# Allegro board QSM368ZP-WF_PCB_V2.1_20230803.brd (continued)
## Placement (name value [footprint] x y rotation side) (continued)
TP1304  TP_1_00mm  [TP_1_00]  19.7 47.75 0 top
TP1401  RESET_N  [TP_1_00]  41.45 30.75 0 top
TP1402  PON_1  [TP_1_00]  38.02 30.75 0 top
TP1403  VOL_DOWN  [TP_1_00]  42.33 29.38 0 top
TP1404  ESC  [TP_1_00]  40.5 29.38 0 top
TP1405  MENU  [TP_1_00]  39.52 30.75 0 top
U0101  -  [ETA1654FSG]  28.65 84.28 180 bottom
U0103  -  [ETA1654FSG]  52.52 85.25 180 bottom
U0104  -  [ETA1654FSG]  35.12 65.38 90 bottom
U0201  NM-ICMEF112P900MFR  [ICMEF112P900MFR]  78.75 92.22 90 top
U0202  SGM2036S-2_8XN5G_TR  [SGM2036S-2_8XN5G_TR_PINS5_2D92X1D6]  81.42 89.65 180 bottom
U0203  SGM2036S-2_8XN5G_TR  [SGM2036S-2_8XN5G_TR_PINS5_2D92X1D6]  77.53 89.6 180 bottom
U0204  -  [ETA3415S6G]  87.58 89.95 180 bottom
U0205  SGM2036S-ADJXN5G/TR  [SGM2036S-ADJXN5G_TR_PINS5_2D92X1D6]  73.88 89.62 180 bottom
U0206  NM-ICMEF112P900MFR  [ICMEF112P900MFR]  97.6 92.12 90 top
U0207  NM-ICMEF112P900MFR  [ICMEF112P900MFR]  93.9 92.12 90 top
U0208  NM-ICMEF112P900MFR  [ICMEF112P900MFR]  82.45 92.25 90 top
U0209  NM-ICMEF112P900MFR  [ICMEF112P900MFR]  90.2 92.12 90 top
U0210  NM-ICMEF112P900MFR  [ICMEF112P900MFR]  86.15 92.22 90 top
U0304  -  [WS4612EDA-5_TR]  33.15 17.18 90 bottom
U0403  NM-ICMEF112P900MFR  [ICMEF112P900MFR]  14.88 16.45 270 top
U0404  NM-ICMEF112P900MFR  [ICMEF112P900MFR]  7.28 16.45 270 top
U0405  -  [PNMT60V02]  6.65 19.12 0 bottom
U0407  NM-PNMT60V02  [PNMT60V02]  49.77 96.08 180 bottom
U0408  NM-ICMEF112P900MFR  [ICMEF112P900MFR]  3.48 16.43 270 top
U0409  SGM3756YTDI6G/TR  [SGM3756YTDI6G_TR_PINS7_2X2]  70.28 87.7 0 top
U0410  NM-PNMT60V02  [PNMT60V02]  51.77 93.08 0 bottom
U0411  NM-ICMEF112P900MFR  [ICMEF112P900MFR]  11.07 16.45 270 top
U0413  -  [PNMT60V02]  10.18 19.18 0 bottom
U0501  SGM2036S-2_8XN5G_TR  [SGM2036S-2_8XN5G_TR_PINS5_2D92X1D6]  64.83 86.78 180 bottom
U0502  SGM2036S-2_8XN5G_TR  [SGM2036S-2_8XN5G_TR_PINS5_2D92X1D6]  17.57 96.92 270 top
U0503  NM-ETA5053V180DF1E  [ETA5053V180DF1E]  15.6 92.4 90 top
U0504  SGM3756YTDI6G/TR  [SGM3756YTDI6G_TR_PINS7_2X2]  62.58 71 0 bottom
U0601  NM-WS4612EDA-5_TR  [WS4612EDA-5_TR]  77.47 26.7 90 bottom
U0602  NM-WS4612EDA-5_TR  [WS4612EDA-5_TR]  39.42 22.73 90 bottom
U0603  NM-WS4612EDA-5_TR  [WS4612EDA-5_TR]  70.22 26.65 90 bottom
U0604  -  [ETA1654FSG]  38.1 49.25 90 bottom
U0701  -  [ETA1654FSG]  69.25 32.92 180 bottom
U0702  -  [TXB0104PWR]  91.45 60.05 90 bottom
U0901  -  [G2401CG]  104.42 29 0 bottom
U0902  -  [YT8531C]  104.67 43.52 90 bottom
U1001  NM-CS86552E  [CS86552E]  12.62 67.17 90 bottom
U1002  WMM7037ATSN0-4/TR  [WMM7037ATSN0]  15.35 88.05 270 top
U1101  NM-SIT3088EESA  [SIT3088EESA]  104.53 64.1 90 bottom
U1102  -  [LSF0204YZPR]  103.75 56.88 180 bottom
U1103  NM-UM3232EEUE  [UM3232EEUE]  107.12 75.25 0 bottom
U1201  Stud_Mechanical-tooth_M2_L4.35_XD_R1  [TP-NUU-M3_15X6_00X4_35MM]  73.15 40.08 180 bottom
U1202  Stud_Mechanical-tooth_M2_L4.35_XD_R1  [TP-NUU-M3_15X6_00X4_35MM]  19.15 40.08 180 bottom
U1203  Stud_Mechanical-tooth_M2_L4.35_XD_R1  [TP-NUU-M3_15X6_00X4_35MM]  73.15 66.08 180 bottom
U1204  NM-X1B000311000100  [X1B000311000100_PINS10_3D2X2D5]  85.1 70.2 270 bottom
U1205  Stud_Mechanical-tooth_M2_L4.35_XD_R1  [TP-NUU-M3_15X6_00X4_35MM]  19.15 66.08 180 bottom
U1301  SG368ZWFNA-G55-UNNNA  [SG368Z]  46.15 53.08 180 top
U1401  U.FL-R-SMT-1(80)  [RF-CON-818000117]  30.85 25.43 180 top
X0901  -  [Q22FA1280021400]  111.45 43.02 270 bottom

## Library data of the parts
B0101 B0503 B1002 = B
B0201 B0202 B0203 B0204 B0205 B0206 R0116 R0203 R0204 R0209 R0223 R0229 R0309 R0607 R0618 R0624 R0936 R1455 R1466-R1469 = R-0402_0R
B0501 B0502 = R-0402_NM
B0901 B1001 B1003-B1005 = B-0603_H0_95
BAT1201 = MS621FE-FL11E_0
C0102 C0103 C0104 C0112 C0119 C0122 C0124 C0128 C0211 C0303 C0319 C0404 C0406 C0413 C0502 C0506 C0516 C0519 C0524 C0526 C0601 C0602 C0606 C0607 C0609 C0613 C0614 C0619 C0701 C0702 C0705 C0706 C0708 C0709 C0714 C0715 C0716 C0802 C0803 C0804 C0805 C0806 C0901 C0903 C0909 C0912 C0920 C0921 C1001 C1004 C1005 C1007 C1008 C1010-C1012 C1015-C1017 C1021 C1103-C1105 C1110 C1111 C1113 C1204 C1304 = C
C0105 C0106 C0107 C0109 C0123 C0126 C0352 C0354 C0363 C0401 C0402 C0410 C0512 C0605 C0611 C0615 C0623 C1302 = c-0603_22_47uf_H1_00
C0108 C0110 C0115 C0116 C0118 C0121 C0127 C0520 C0522 C0622 C0624 C0704 C1055 C1056 = C-0805_H1_45
C0111 C0113 C0114 C0353 C0355 C0360 C0361 C0362 C0618 C0620 C0621 = C: signal model: C_C-0402_100NF_+/-10%_16V_100nF_+/-10%_16V
C0201 C0202 C0210 C0214 C0299 C0403 C0405 C0408 C0501 C0507 C0511 C0514 C0517 C0518 C0527 C0528 C0530 C0533 C1006 C1009 C1023 C1025 C1099 C1101 C1106 = C-0402
C0203 C0206 C0407 C0409 C0508 C0521 C0523 = C-0603
C0204 C0207 C0209 C0212 C0213 C0215 C0216 C0217 C0535 C0711 C0902 C0911 C0916 C0917 C0918 = C-0402_X5R_10UF
C0205 C0208 = c-0402_4_7_10uf_H0_70
C0301 C0307 C0309 C0707 C0801 C0904 C0905 C0906 C0907 C0908 C0910 C0913 C0914 C0915 C0919 C0922 C0986 C0987 C0988 C1014 C1024 C1102 C1108 = C: signal model: C_C-0402_100NF_+/-10%_10V_100nF_+/-10%_10V
C0412 C0504 = C-0805
C0505 C0509 C0510 C0513 C0515 C0525 C0529 C0531 C0532 C0534 C0536 C0603 C0604 C0617 C1003 C1201-C1203 = C: signal model: C_C-0402_NM_100NF_+/-10%_16V_NM_100nF_+/-10%_16V
C0703 = C: signal model: C_C-0402_NM_220NF_+/-10%_10V_NM_220nF_+/-10%_10V
C0710 C1333 = C-3528TB-M
C0712 C0713 = c-0603_22_47uf_H1_00: signal model: C_C-0402_100NF_+/-10%_10V_100nF_+/-10%_10V
C0717 = C-0805_H1_45: signal model: C_C-0402_NM_220NF_+/-10%_10V_NM_220nF_+/-10%_10V
C1013 = C-1210
C1018 C1020 C1022 C1026 C1027 = C-0603_H1_00
C1303 = C-3528TB-M: signal model: DEFAULT_CAPACITOR_1e+08pF_2_1
C1306 = C: signal model: DEFAULT_CAPACITOR_100000pF_2_1
C1401 C1402 = C-0402_X5R_1UF
D0101 = SMAJ18CA
D0102 D0705 D0706 = LTST-C193KRKT-5A
D0301 D0359 D0904 D0906 = ESD5304D-10_TR
D0302 D0303 D0353 D0356 D0357 D0601 D0603 D0606 D0608 D0702 D0704 D0801 D0802 D0804 D0807 D0808 D0809 D0810 D0901 D0903 = ESDU5V0F1
D0354 D0355 D0358 D0602 D0605 = PTVSHC2EN7VU
D0401 D0402 = PSBD3D40V1H
D0403 D0405 D0508 = RB160VA-40
D0404 Q0405 U0405 U0407 U0410 U0413 = PNMT60V02
D0406 D0407 D0408 D0410 = PESDNC2FD7VB
D0501 D0503 D0505 D0507 D0701 D0703 D0902 D0905 Q0402 Q0403 Q0404 Q1101 Q1102 = DTC043ZEBTL
D0502 D0506 D0511 D0512 D0514 U0201 U0206 U0207 U0208 U0209 U0210 U0403 U0404 U0408 U0411 = ICMEF112P900MFR
D0504 D0509 D0510 D0513 D1104 D1106 = PESD5V0S1BL
D0803 = F-CESDLC5V0M5
D0806 D1001-D1004 D1050 D1051 D1201 D1202 D1255 D1256 = PESDNC2FD5VBH
D1301 = PTVSHC3N4V5B
F0101 = 2410WNF1000A125V
HOLE1201-HOLE1206 = PTH_cir2_50_4_50
J0101 = DC-305B209
J0102 = C2542VD10210G0101PK
J0201 J0202 = FH26W-25S-0_3SHW_60
J0301 = W-N3-SC90-012
J0302 = WX4558105890
J0401 = WXHDMI2034A36
J0402 = 50552-00601-001
J0403 = 50552-04001-001
J0501 = AXE530127
J0502 = 50552-03001-001
J0503 = 6298706220883
J0601 = W-USB2-SZ90-A10
J0701 = MINI-PCIE-CON
J0702 = 480995701
J0801 = MUP-M615-1
J0802 = MUP-C792-3
J0901 = 11201208210120021
J1001 = C2001VD10601T0101PB
J1002 = KR-CKX-3_5-335D-F
J1101 = PH2542-3-115D30T
J1201 = C2012VD21222T0101PC
L0101 L0102 L0103 L0201 L0401 L0501 L0601 L0701 = L
L0702 = SDMM0806H-2-900T
L0901 = L-2016
LAB1201 = SILKLABEL_25_00x10_00
PCB1201 = BOARD_PCB
Q0401 = WPM3027
Q0501 Q0502 = DMG2305UX-7
R0101 R0102 R0103 R0104 R0105 R0108 R0110 R0112 R0113 R0114 R0115 R0117 R0207 R0208 R0212 R0214 R0219 R0221 R0222 R0224 R0226 R0227 R0228 R0305 R0308 R0313 R0325 R0401 R0402 R0403 R0404 R0405 R0407 R0409 R0413 R0414 R0415 R0416 R0417 R0420 R0421 R0422 R0424 R0425 R0426 R0427 R0428 R0429 R0430 R0503 R0504 R0505 R0506 R0507 R0508 R0510 R0512 R0513 R0515 R0517 R0518 R0519 R0522 R0523 R0528 R0529 R0530 R0602 R0603 R0604 R0606 R0610 R0612 R0613 R0614 R0615 R0617 R0620 R0622 R0623 R0698 R0699 R0701 R0702 R0704 R0705 R0706 R0707 R0708 R0710 R0711 R0714 R0716 R0717 R0718 R0719 R0720 R0722 R0723 R0724 R0725 R0727 R0729 R0731 R0732 R0807 R0809 R0866 R0901 R0902 R0904 R0905 R0907 R0908 R0909 R0911 R0912 R0913 R0914 R0916 R0917 R0918 R0919 R0921 R0922 R0924 R0925 R0926 R0927 R0928 R0929 R0934 R0938 R0940 R0941 R0942 R0943 R0944 R0946 R0947 R0952 R0953 R0956 R1004 R1007 R1011 R1014 R1015 R1017 R1022 R1024 R1103 R1105 R1107 R1111 R1113 R1117 R1120 R1123 R1129 R1132-R1134 R1203 R1204 R1206-R1208 R1301 R1456 = R-0402
R0106 R0120 = R-1206
R0166 R0406 R0418 R0644 R0703 R0709 R0713 R0733 R0933 R0935 R0948 R0950 R0951 R0988 R1125 R1155 R1157 R1159 R1161 R1202 R1205 R1210 R1211 R1457 = R-0402: signal model: R-0402_R-0402_NM_0R_+/-5%_1/16W_NM_0R_+/-5%_1/16W
R0255 R0256 R0257 R0258 R0259 R0260 R0261 R0262 R0263 R0264 R0265 R0266 R0319 R0322 R0323 R0340 R0341 R0455 R0457 R0458 R0459 R0460 R0461 R0462 R0466 R0511 R0526 R0566 R0567 R0568 R0569 R0570 R0571 R0572 R0573 R0574 R0575 R0601 R0608 R0611 R0616 R0619 R0621 R0721 R0726 R0805 R0910 R0915 R0923 R0930 R0931 R0939 R0949 R0954 R1003 R1010 R1018 R1023 R1099 R1115 R1119 R1126 R1130 R1156 R1158 R1160 R1162 R1407 = R-0402: signal model: R-0402_R-0402_0R_+/-5%_1/16W_0R_+/-5%_1/16W
R0302 R0312 R0516 R0527 R0804 = R
R0366 R0408 R0509 R0525 R0666 R0677 R0678 R0715 R0728 R0803 R0808 R0810 R0813 R1005 R1012 R1121 = R-0603
R0712 R0730 R0801 R0802 R0806 R0811 R0814 = R-0402: signal model: R-0402_R-0402_33R_+/-5%_1/16W_33R_+/-5%_1/16W
R0903 R0906 R0920 R0932 R0945 R0955 R1302-R1307 = R-0402: signal model: R-0402_R-0402_22R_+/-5%_1/16W_22R_+/-5%_1/16W
R1002 R1008 R1016 R1019-R1021 = R-0805
R1401-R1406 R1408 R1409 = R-0402: signal model: DEFAULT_RESISTOR_2.200000OHM_2_1
S0301 S1201 = SSAJ120100
S1202 = THDP08-060AB1
TP0101 TP0102 TP0103 TP0301 TP0302 TP0303 TP0502 TP0504 TP1201-TP1203 TP1301-TP1304 TP1401-TP1405 = TP_1_00
TP0104 = TP_2_20
TP0501 TP0503 TP0701 TP0702 TP0703 = TP
U0101 U0103 U0104 U0604 U0701 = ETA1654FSG
U0202 U0203 U0501 U0502 = SGM2036S-2_8XN5G_TR
U0204 = ETA3415S6G
U0205 = SGM2036S-ADJXN5G_TR
U0304 U0601 U0602 U0603 = WS4612EDA-5_TR
U0409 U0504 = SGM3756YTDI6G_TR
U0503 = ETA5053V180DF1E
U0702 = TXB0104PWR
U0901 = FC1503NL
U0902 = YT8531C
U1001 = CS86552E
U1002 = WMM7037ATSN0
U1101 = SIT3088EESA
U1102 = LSF0204YZPR
U1103 = UM3232EEUE
U1201-U1203 U1205 = tp-nuu-m3_15x6_00x4_35mm
U1204 = X1B000311000100
U1301 = SG368Z
U1401 = RF-CON-818000117
X0901 = Q22FA1280021400

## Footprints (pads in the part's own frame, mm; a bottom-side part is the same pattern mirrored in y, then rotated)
2410WNF1000A125V
  rect 1.96x3.15 smd: 1(-2.455,0) 2(2.455,0)
3528TB-M
  rect 1.45x2.8 smd: 1(-1.325,0) 2(1.325,0)
50552-00601-001_PINS8_7D5X3D4
  rect 0.4x1.6 smd: 1(-1.25,1.3) 2(-0.75,-1.1) 3(-0.25,1.3) 4(0.25,-1.1) 5(0.75,1.3) 6(1.25,-1.1)
  rect 1.4x2.9 smd: 7(-2.95,0.1) 8(2.95,0.1)
50552-03001-001_PINS32_19D5X3D4
  rect 0.4x1.6 smd: 1(-7.25,1.3) 2(-6.75,-1.1) 3(-6.25,1.3) 4(-5.75,-1.1) 5(-5.25,1.3) 6(-4.75,-1.1) 7(-4.25,1.3) 8(-3.75,-1.1) 9(-3.25,1.3) 10(-2.75,-1.1) 11(-2.25,1.3) 12(-1.75,-1.1) 13(-1.25,1.3) 14(-0.75,-1.1) 15(-0.25,1.3) 16(0.25,-1.1) 17(0.75,1.3) 18(1.25,-1.1) 19(1.75,1.3) 20(2.25,-1.1) 21(2.75,1.3) 22(3.25,-1.1) 23(3.75,1.3) 24(4.25,-1.1) 25(4.75,1.3) 26(5.25,-1.1) 27(5.75,1.3) 28(6.25,-1.1) 29(6.75,1.3) 30(7.25,-1.1)
  rect 1.4x2.9 smd: 31(-8.95,0.1) 32(8.95,0.1)
50552-04001-001_PINS42_24D5X3D4
  rect 0.4x1.6 smd: 1(-9.75,1.3) 2(-9.25,-1.1) 3(-8.75,1.3) 4(-8.25,-1.1) 5(-7.75,1.3) 6(-7.25,-1.1) 7(-6.75,1.3) 8(-6.25,-1.1) 9(-5.75,1.3) 10(-5.25,-1.1) 11(-4.75,1.3) 12(-4.25,-1.1) 13(-3.75,1.3) 14(-3.25,-1.1) 15(-2.75,1.3) 16(-2.25,-1.1) 17(-1.75,1.3) 18(-1.25,-1.1) 19(-0.75,1.3) 20(-0.25,-1.1) 21(0.25,1.3) 22(0.75,-1.1) 23(1.25,1.3) 24(1.75,-1.1) 25(2.25,1.3) 26(2.75,-1.1) 27(3.25,1.3) 28(3.75,-1.1) 29(4.25,1.3) 30(4.75,-1.1) 31(5.25,1.3) 32(5.75,-1.1) 33(6.25,1.3) 34(6.75,-1.1) 35(7.25,1.3) 36(7.75,-1.1) 37(8.25,1.3) 38(8.75,-1.1) 39(9.25,1.3) 40(9.75,-1.1)
  rect 1.4x2.9 smd: 41(-11.45,0.1) 42(11.45,0.1)
480995701
  round 1.6 hole 1.6 unplated: (-12.1,0)
  round 1.1 hole 1.1 unplated: (12.1,0)
  rect 4.8x3 smd: 1(-12.1,-3.15) 2(12.1,-3.15) 3(12.1,3.15) 4(-12.1,3.15)
6298706220883
  rect 0.3x1.1 smd: 1(1.25,0) 2(0.75,0) 3(0.25,0) 4(-0.25,0) 5(-0.75,0) 6(-1.25,0)
  rect 0.42x1.3 smd: 7(-2.47,-2.87) 8(2.47,-2.87)
11201208210120021
  round 3.35 hole 3.35 unplated: (-6.35,-0.06) (6.35,-0.06)
  round 1.5 hole 0.9: 1(3.57,2.48) 2(2.55,4.26) 3(1.53,2.48) 4(0.51,4.26) 5(-0.51,2.48) 6(-1.53,4.26) 7(-2.55,2.48) 8(-3.57,4.26)
  round 1.7 hole 1: 9(6.86,9.07) 10(4.57,9.07) 11(-4.57,9.07) 12(-6.86,9.07)
  round 3.2 hole 1.8: 15(8.13,3.5) 16(-8.13,3.5)
AXE530127
  rect 0.23x0.5 smd: 1(2.8,1.2) 2(2.4,1.2) 3(2,1.2) 4(1.6,1.2) 5(1.2,1.2) 6(0.8,1.2) 7(0.4,1.2) 8(0,1.2) 9(-0.4,1.2) 10(-0.8,1.2) 11(-1.2,1.2) 12(-1.6,1.2) 13(-2,1.2) 14(-2.4,1.2) 15(-2.8,1.2) 16(-2.8,-1.2) 17(-2.4,-1.2) 18(-2,-1.2) 19(-1.6,-1.2) 20(-1.2,-1.2) 21(-0.8,-1.2) 22(-0.4,-1.2) 23(0,-1.2) 24(0.4,-1.2) 25(0.8,-1.2) 26(1.2,-1.2) 27(1.6,-1.2) 28(2,-1.2) 29(2.4,-1.2) 30(2.8,-1.2)
  custom 0.225x0.225 smd: 31(-3.8,-0.99) 32(3.8,-0.99) 33(3.8,0.99) 34(-3.8,0.99)
B-0402
  rect 0.55x0.55 smd: 1(-0.45,0) 2(0.45,0)
B-0603_H0_95
  rect 0.7x0.9 smd: 1(-0.75,0) 2(0.75,0)
BOARD_PCB
  round 0.4 smd: 1(0,0)
C2001VD10601T0101PB
  rect 1.65x1.65 hole 0.85: 1(-5,-0.625)
  round 1.65 hole 0.85: 2(-3,-0.625) 3(-1,-0.625) 4(1,-0.625) 5(3,-0.625) 6(5,-0.625)
C2012VD21222T0101PC
  rect 1.4x1.4 hole 0.8: 1(-11,0.625)
  round 1.4 hole 0.8: 2(-11,-1.375) 3(-9,0.625) 4(-9,-1.375) 5(-7,0.625) 6(-7,-1.375) 7(-5,0.625) 8(-5,-1.375) 9(-3,0.625) 10(-3,-1.375) 11(-1,0.625) 12(-1,-1.375) 13(1,0.625) 14(1,-1.375) 15(3,0.625) 16(3,-1.375) 17(5,0.625) 18(5,-1.375) 19(7,0.625) 20(7,-1.375) 21(9,0.625) 22(9,-1.375) 23(11,0.625) 24(11,-1.375)
C2542VD10210G0101PK
  rect 1.82x1.82 hole 1.02: 1(-1.27,0)
  round 1.82 hole 1.02: 2(1.27,0)
C-0402
  rect 0.55x0.55 smd: 1(-0.45,0) 2(0.45,0)
C-0402_4_7_10UF
  rect 0.525x0.7 smd: 1(-0.463,0) 2(0.463,0)
C-0402_4_7_10UF_H0_70
  rect 0.525x0.7 smd: 1(-0.463,0) 2(0.463,0)
C-0603
  rect 0.7x0.8 smd: 1(-0.75,0) 2(0.75,0)
C-0603_22_47UF_H1_00
  rect 0.7x0.96 smd: 1(-0.75,0) 2(0.75,0)
C-0603_H1_00
  rect 0.7x0.8 smd: 1(-0.75,0) 2(0.75,0)
C-0805
  rect 0.9x1.3 smd: 1(-0.9,0) 2(0.9,0)
C-0805_H1_45
  rect 0.9x1.3 smd: 1(-0.9,0) 2(0.9,0)
C-1206
  rect 1.3x1.6 smd: 1(-1.4,0) 2(1.4,0)
C-1210
  rect 1.2x2 smd: 1(-1.6,0) 2(1.6,0)
CS86552E
  rect 1.215x0.23 smd: 1(-2.567,2.223) 2(-2.567,1.587) 3(-2.567,0.953) 4(-2.567,0.318) 5(-2.567,-0.318) 6(-2.567,-0.953) 7(-2.567,-1.587) 8(-2.567,-2.223) 9(2.567,-2.223) 10(2.567,-1.587) 11(2.567,-0.953) 12(2.567,-0.318) 13(2.567,0.318) 14(2.567,0.953) 15(2.567,1.587) 16(2.567,2.223)
  rect 2.4x3.7 smd: 17(0,0)
DC-305B209
  round 2.4 hole 2.4 unplated: (-1.9,-1.3)
  oval 3.5x2.6 hole 1.7x0.8: 1(4.4,-4.7) 2(4.4,4) 3(4.4,-1.3)
  oval 3.9x2.4 hole 2.1x0.6: 4(-2.9,-4.95) 5(-2.9,4.95)
DMG2305UX-7
  rect 0.8x0.9 smd: 1(-0.95,-1) 2(0.95,-1) 3(0,1)
DTC043ZEBTL
  rect 0.46x0.65 smd: 1(-0.5,-0.525) 2(0.5,-0.525) 3(0,0.525)
ESD5304D-10_TR
  rect 0.2x0.6 smd: 1(-1,-0.4) 2(-0.5,-0.4) 4(0.5,-0.4) 5(1,-0.4) 6(1,0.4) 7(0.5,0.4) 9(-0.5,0.4) 10(-1,0.4)
  rect 0.4x0.7 smd: 3(0,-0.35) 8(0,0.35)
ESDU5V0F1
  rect 0.5x0.4 smd: 1(-0.4,0)
  rect 0.62x0.4 smd: 2(0.34,0)
ETA1654FSG
  rect 0.45x0.3 smd: 1(-0.675,0.5) 2(-0.675,0) 3(-0.675,-0.5) 4(0.675,-0.5) 5(0.675,0) 6(0.675,0.5)
ETA3415S6G
  rect 0.7x0.3 smd: 1(-0.75,0.5) 2(-0.75,0) 3(-0.75,-0.5) 4(0.75,-0.5) 5(0.75,0) 6(0.75,0.5)
ETA5053V180DF1E
  custom 0.077x0.077 smd: 1(-0.375,-0.41) 2(0.375,-0.41) 3(0.375,0.41) 4(-0.375,0.41)
  rect 0.42x0.42 smd rot 45: 5(0,0)
F-CESDLC5V0M5
  rect 0.3x0.3 smd: 1(-0.5,-0.7) 2(0,-0.7) 3(0.5,-0.7) 4(0.5,0.7) 5(0,0.7) 6(-0.5,0.7)
FH26W-25S-0_3SHW_60
  rect 0.3x0.8 smd: 1(-3.6,-1.4) 3(-3,-1.4) 5(-2.4,-1.4) 7(-1.8,-1.4) 9(-1.2,-1.4) 11(-0.6,-1.4) 13(0,-1.4) 15(0.6,-1.4) 17(1.2,-1.4) 19(1.8,-1.4) 21(2.4,-1.4) 23(3,-1.4) 25(3.6,-1.4)
  rect 0.3x0.65 smd: 2(-3.3,1.475) 4(-2.7,1.475) 6(-2.1,1.475) 8(-1.5,1.475) 10(-0.9,1.475) 12(-0.3,1.475) 14(0.3,1.475) 16(0.9,1.475) 18(1.5,1.475) 20(2.1,1.475) 22(2.7,1.475) 24(3.3,1.475)
  rect 0.45x1 smd: 26(-4.325,-1.1) 27(4.325,-1.1)
G2401CG
  rect 0.64x1.78 smd: 1(-5.445,-4.71) 2(-4.455,-4.71) 3(-3.465,-4.71) 4(-2.475,-4.71) 5(-1.485,-4.71) 6(-0.495,-4.71) 7(0.495,-4.71) 8(1.485,-4.71) 9(2.475,-4.71) 10(3.465,-4.71) 11(4.455,-4.71) 12(5.445,-4.71) 13(5.445,4.71) 14(4.455,4.71) 15(3.465,4.71) 16(2.475,4.71) 17(1.485,4.71) 18(0.495,4.71) 19(-0.495,4.71) 20(-1.485,4.71) 21(-2.475,4.71) 22(-3.465,4.71) 23(-4.455,4.71) 24(-5.445,4.71)
ICMEF112P900MFR
  rect 0.6x0.3 smd: 1(-0.675,0.275) 2(-0.675,-0.275) 3(0.675,0.275) 4(0.675,-0.275)
  rect 0.3x0.6 smd: 5(0,0.54) 6(0,-0.54)
KR-CKX-3_5-335D-F_PINS6_13D9X9D5
  round 1.3 hole 1.3 unplated: (-3.25,0.55) (3.25,0.55)
  round 2 hole 1.2: 1(-0.25,1.65) 2(-3.85,-3.35) 3(1.35,-6.45) 4(2.85,-4.45) 5(4.25,-6.45) 6(-1.85,-6.45)
L-2016
  rect 0.7x1.8 smd: 1(-0.75,0) 2(0.75,0)
L-2520
  rect 0.7x2.1 smd: 1(-1,0) 2(1,0)
L-SPM6530T-3R3M
  rect 1.85x3.4 smd: 1(-2.775,0) 2(2.775,0)
LSF0204YZPR
  round 0.25 smd: A1(0.75,0.5) A2(0.75,0) A3(0.75,-0.5) B1(0.25,0.5) B2(0.25,0) B3(0.25,-0.5) C1(-0.25,0.5) C2(-0.25,0) C3(-0.25,-0.5) D1(-0.75,0.5) D2(-0.75,0) D3(-0.75,-0.5)
LTST-C193KRKT-5A
  rect 0.8x0.8 smd: 1(-0.75,0) 2(0.75,0)
MINI-PCIE-CON
  round 1.6 hole 1.6 unplated: (-12.5,0)
  round 1.1 hole 1.1 unplated: (12.5,0)
  rect 0.6x2 smd: 1(-11.8,-4.1) 2(-11.4,4.1) 3(-11,-4.1) 4(-10.6,4.1) 5(-10.2,-4.1) 6(-9.8,4.1) 7(-9.4,-4.1) 8(-9,4.1) 9(-8.6,-4.1) 10(-8.2,4.1) 11(-7.8,-4.1) 12(-7.4,4.1) 13(-7,-4.1) 14(-6.6,4.1) 15(-6.2,-4.1) 16(-5.8,4.1) 17(-2.2,-4.1) 18(-1.8,4.1) 19(-1.4,-4.1) 20(-1,4.1) 21(-0.6,-4.1) 22(-0.2,4.1) 23(0.2,-4.1) 24(0.6,4.1) 25(1,-4.1) 26(1.4,4.1) 27(1.8,-4.1) 28(2.2,4.1) 29(2.6,-4.1) 30(3,4.1) 31(3.4,-4.1) 32(3.8,4.1) 33(4.2,-4.1) 34(4.6,4.1) 35(5,-4.1) 36(5.4,4.1) 37(5.8,-4.1) 38(6.2,4.1) 39(6.6,-4.1) 40(7,4.1) 41(7.4,-4.1) 42(7.8,4.1) 43(8.2,-4.1) 44(8.6,4.1) 45(9,-4.1) 46(9.4,4.1) 47(9.8,-4.1) 48(10.2,4.1) 49(10.6,-4.1) 50(11,4.1) 51(11.4,-4.1) 52(11.8,4.1)
  rect 2.3x3.2 smd: 53(-14.65,-3.5) 54(14.65,-3.5)
MS621FE-FL11E
  rect 2x0.5 smd: 1(-0.1,0.75)
  rect 2.2x0.5 smd: 2(-0.2,-0.75)
MUP-C792-3
  rect 2.61x1.56 smd: 1(14.23,7.31) 2(1.6,7.31) 3(1.6,-9.37) 4(14.23,-9.37)
  rect 1.35x0.9 smd: C1(17.105,-3.79) C2(17.105,-1.25) C3(17.105,1.29) C4(17.105,3.83) C5(17.105,-2.52) C6(17.105,0.02) C7(17.105,2.56) C8(17.105,5.1) CD(17.105,6.37)
MUP-M615-1
  rect 1.3x1.4 smd: 1(-4.975,7.225) 2(0.725,7.225)
  rect 1.4x1.9 smd: 3(-6.575,-5.925) 4(6.575,-6.925)
  rect 1x0.95 smd: CD(-3.585,7.45)
  rect 0.8x1.5 smd: P1(1.915,-3.635) P2(0.815,-3.235) P3(-0.285,-3.635) P4(-1.385,-3.835) P5(-2.485,-3.635) P6(-3.585,-3.835) P7(-4.685,-3.635) P8(-5.785,-3.635)
PESD5V0S1BL
  rect 0.4x0.7 smd: 1(-0.35,0) 2(0.35,0)
PESDNC2FD5VBH
  rect 0.5x0.6 smd: 1(-0.35,0) 2(0.35,0)
PESDNC2FD7VB
  rect 0.5x0.6 smd: 1(-0.35,0) 2(0.35,0)
PH2542-3-115D30T
  rect 1.82x1.82 hole 1.02: 1(-2.54,-1.27)
  round 1.82 hole 1.02: 2(-2.54,1.27) 3(0,-1.27) 4(0,1.27) 5(2.54,-1.27) 6(2.54,1.27)
PNMT60V02
  rect 0.435x0.6 smd: 1(-0.955,-0.95) 2(0.955,-0.95) 3(0,0.95)
PSBD3D40V1H
  rect 0.8x0.9 smd: 1(-1.1,0) 2(1.1,0)
PTH_CIR2_50_4_50
  round 4.5 hole 2.5: 1(0,0)
PTVSHC2EN7VU
  rect 0.625x1 smd: 1(-0.613,0) 2(0.613,0)
PTVSHC3N4V5B
  rect 0.4x0.5 smd: 1(-0.65,-0.838) 2(0.65,-0.838)
  custom 0.338x0.338 smd: 3(0,0.412)
Q22FA1280021400
  rect 0.95x0.85 smd: 1(-0.725,-0.575) 2(0.725,-0.575) 3(0.725,0.575) 4(-0.725,0.575)
R-0402
  rect 0.55x0.55 smd: 1(-0.45,0) 2(0.45,0)
R-0603
  rect 0.7x0.8 smd: 1(-0.75,0) 2(0.75,0)
R-0805
  rect 0.9x1.3 smd: 1(-0.9,0) 2(0.9,0)
R-1206
  rect 1.3x1.6 smd: 1(-1.4,0) 2(1.4,0)
RB160VA-40
  rect 1.1x2 smd: 1(0,0.65)
  rect 1.1x0.8 smd: 2(0,-1.25)
RF-CON-818000117
  rect 1x1.05 smd: 1(0,1.525) 3(0,-1.525)
  rect 1.05x2.2 smd: 2(-1.475,0) 4(1.475,0)
SDMM0806H-2-900T
  rect 0.3x0.3 smd: 1(0.25,0.3) 2(0.25,-0.3) 3(-0.25,0.3) 4(-0.25,-0.3)
SG368Z
  rect 0.7x1 smd: 1(-20.8,-20.2) 2(-19.2,-20.2) 3(-18.4,-18.3) 4(-17.6,-20.2) 5(-16.8,-18.3) 6(-16,-16.4) 7(-16,-20.2) 8(-15.2,-18.3) 9(-14.4,-16.4) 10(-13.6,-14.5) 11(-14.4,-20.2) 12(-13.6,-18.3) 13(-12.8,-16.4) 14(-12,-14.5) 15(-11.2,-12.6) 16(-12.8,-20.2) 17(-12,-18.3) 18(-11.2,-16.4) 19(-10.4,-14.5) 20(-9.6,-12.6) 21(-11.2,-20.2) 22(-10.4,-18.3) 23(-9.6,-16.4) 24(-8.8,-14.5) 25(-8,-12.6) 26(-9.6,-20.2) 27(-8.8,-18.3) 28(-8,-16.4) 29(-7.2,-14.5) 30(-6.4,-12.6) 31(-8,-20.2) 32(-7.2,-18.3) 33(-6.4,-16.4) 34(-5.6,-14.5) 35(-4.8,-12.6) 36(-6.4,-20.2) 37(-5.6,-18.3) 38(-4.8,-16.4) 39(-4,-14.5) 40(-3.2,-12.6) 41(-4.8,-20.2) 42(-4,-18.3) 43(-3.2,-16.4) 44(-2.4,-14.5) 45(-1.6,-12.6) 46(-3.2,-20.2) 47(-2.4,-18.3) 48(-1.6,-16.4) 49(-0.8,-14.5) 50(0,-12.6) 51(-1.6,-20.2) 52(-0.8,-18.3) 53(0,-16.4) 54(0.8,-14.5) 55(1.6,-12.6) 56(0,-20.2) 57(0.8,-18.3) 58(1.6,-16.4) 59(2.4,-14.5) 60(3.2,-12.6) 61(1.6,-20.2) 62(2.4,-18.3) 63(3.2,-16.4) 64(4,-14.5) 65(4.8,-12.6) 66(3.2,-20.2) 67(4,-18.3) 68(4.8,-16.4) 69(5.6,-14.5) 70(6.4,-12.6) 71(4.8,-20.2) 72(5.6,-18.3) 73(6.4,-16.4) 74(7.2,-14.5) 75(8,-12.6) 76(6.4,-20.2) 77(7.2,-18.3) 78(8,-16.4) 79(8.8,-14.5) 80(9.6,-12.6) 81(8,-20.2) 82(8.8,-18.3) 83(9.6,-16.4) 84(10.4,-14.5) 85(11.2,-12.6) 86(9.6,-20.2) 87(10.4,-18.3) 88(11.2,-16.4) 89(12,-14.5) 90(11.2,-20.2) 91(12,-18.3) 92(12.8,-16.4) 93(13.6,-14.5) 94(12.8,-20.2) 95(13.6,-18.3) 96(14.4,-16.4) 97(14.4,-20.2) 98(15.2,-18.3) 99(16,-16.4) 100(16,-20.2) 101(16.8,-18.3) 102(17.6,-20.2) 103(18.4,-18.3) 104(19.2,-20.2) 105(20.8,-20.2) 196(20.8,20.2) 197(19.2,20.2) 198(18.4,18.3) 199(17.6,20.2) 200(16.8,18.3) 201(16,16.4) 202(16,20.2) 203(15.2,18.3) 204(14.4,16.4) 205(13.6,14.5) 206(14.4,20.2) 207(13.6,18.3) 208(12.8,16.4) 209(12,14.5) 210(11.2,12.6) 211(12.8,20.2) 212(12,18.3) 213(11.2,16.4) 214(10.4,14.5) 215(9.6,12.6) 216(11.2,20.2) 217(10.4,18.3) 218(9.6,16.4) 219(8.8,14.5) 220(8,12.6) 221(9.6,20.2) 222(8.8,18.3) 223(8,16.4) 224(7.2,14.5) 225(6.4,12.6) 226(8,20.2) 227(7.2,18.3) 228(6.4,16.4) 229(5.6,14.5) 230(4.8,12.6) 231(6.4,20.2) 232(5.6,18.3) 233(4.8,16.4) 234(4,14.5) 235(3.2,12.6) 236(4.8,20.2) 237(4,18.3) 238(3.2,16.4) 239(2.4,14.5) 240(1.6,12.6) 241(3.2,20.2) 242(2.4,18.3) 243(1.6,16.4) 244(0.8,14.5) 245(0,12.6) 246(1.6,20.2) 247(0.8,18.3) 248(0,16.4) 249(-0.8,14.5) 250(-1.6,12.6) 251(0,20.2) 252(-0.8,18.3) 253(-1.6,16.4) 254(-2.4,14.5) 255(-3.2,12.6) 256(-1.6,20.2) 257(-2.4,18.3) 258(-3.2,16.4) 259(-4,14.5) 260(-4.8,12.6) 261(-3.2,20.2) 262(-4,18.3) 263(-4.8,16.4) 264(-5.6,14.5) 265(-6.4,12.6) 266(-4.8,20.2) 267(-5.6,18.3) 268(-6.4,16.4) 269(-7.2,14.5) 270(-8,12.6) 271(-6.4,20.2) 272(-7.2,18.3) 273(-8,16.4) 274(-8.8,14.5) 275(-9.6,12.6) 276(-8,20.2) 277(-8.8,18.3) 278(-9.6,16.4) 279(-10.4,14.5) 280(-11.2,12.6) 281(-9.6,20.2) 282(-10.4,18.3) 283(-11.2,16.4) 284(-12,14.5) 285(-11.2,20.2) 286(-12,18.3) 287(-12.8,16.4) 288(-13.6,14.5) 289(-12.8,20.2) 290(-13.6,18.3) 291(-14.4,16.4) 292(-14.4,20.2) 293(-15.2,18.3) 294(-16,16.4) 295(-16,20.2) 296(-16.8,18.3) 297(-17.6,20.2) 298(-18.4,18.3) 299(-19.2,20.2) 300(-20.8,20.2)
  rect 1x0.7 smd: 106(22.2,-18.4) 107(22.2,-16.8) 108(20.3,-16) 109(22.2,-15.2) 110(20.3,-14.4) 111(18.4,-13.6) 112(22.2,-13.6) 113(20.3,-12.8) 114(18.4,-12) 115(16.5,-11.2) 116(22.2,-12) 117(20.3,-11.2) 118(18.4,-10.4) 119(16.5,-9.6) 120(14.6,-8.8) 121(22.2,-10.4) 122(20.3,-9.6) 123(18.4,-8.8) 124(16.5,-8) 125(14.6,-7.2) 126(22.2,-8.8) 127(20.3,-8) 128(18.4,-7.2) 129(16.5,-6.4) 130(14.6,-5.6) 131(22.2,-7.2) 132(20.3,-6.4) 133(18.4,-5.6) 134(16.5,-4.8) 135(14.6,-4) 136(22.2,-5.6) 137(20.3,-4.8) 138(18.4,-4) 139(16.5,-3.2) 140(14.6,-2.4) 141(22.2,-4) 142(20.3,-3.2) 143(18.4,-2.4) 144(16.5,-1.6) 145(14.6,-0.8) 146(22.2,-2.4) 147(20.3,-1.6) 148(18.4,-0.8) 149(16.5,0) 150(14.6,0.8) 151(22.2,-0.8) 152(20.3,0) 153(18.4,0.8) 154(16.5,1.6) 155(14.6,2.4) 156(22.2,0.8) 157(20.3,1.6) 158(18.4,2.4) 159(16.5,3.2) 160(14.6,4) 161(22.2,2.4) 162(20.3,3.2) 163(18.4,4) 164(16.5,4.8) 165(14.6,5.6) 166(22.2,4) 167(20.3,4.8) 168(18.4,5.6) 169(16.5,6.4) 170(14.6,7.2) 171(22.2,5.6) 172(20.3,6.4) 173(18.4,7.2) 174(16.5,8) 175(14.6,8.8) 176(22.2,7.2) 177(20.3,8) 178(18.4,8.8) 179(16.5,9.6) 180(22.2,8.8) 181(20.3,9.6) 182(18.4,10.4) 183(16.5,11.2) 184(22.2,10.4) 185(20.3,11.2) 186(18.4,12) 187(22.2,12) 188(20.3,12.8) 189(18.4,13.6) 190(22.2,13.6) 191(20.3,14.4) 192(22.2,15.2) 193(20.3,16) 194(22.2,16.8) 195(22.2,18.4) 301(-22.2,18.4) 302(-22.2,16.8) 303(-20.3,16) 304(-22.2,15.2) 305(-20.3,14.4) 306(-18.4,13.6) 307(-22.2,13.6) 308(-20.3,12.8) 309(-18.4,12) 310(-16.5,11.2) 311(-22.2,12) 312(-20.3,11.2) 313(-18.4,10.4) 314(-16.5,9.6) 315(-14.6,8.8) 316(-22.2,10.4) 317(-20.3,9.6) 318(-18.4,8.8) 319(-16.5,8) 320(-14.6,7.2) 321(-22.2,8.8) 322(-20.3,8) 323(-18.4,7.2) 324(-16.5,6.4) 325(-14.6,5.6) 326(-22.2,7.2) 327(-20.3,6.4) 328(-18.4,5.6) 329(-16.5,4.8) 330(-14.6,4) 331(-22.2,5.6) 332(-20.3,4.8) 333(-18.4,4) 334(-16.5,3.2) 335(-14.6,2.4) 336(-22.2,4) 337(-20.3,3.2) 338(-18.4,2.4) 339(-16.5,1.6) 340(-14.6,0.8) 341(-22.2,2.4) 342(-20.3,1.6) 343(-18.4,0.8) 344(-16.5,0) 345(-14.6,-0.8) 346(-22.2,0.8) 347(-20.3,0) 348(-18.4,-0.8) 349(-16.5,-1.6) 350(-14.6,-2.4) 351(-22.2,-0.8) 352(-20.3,-1.6) 353(-18.4,-2.4) 354(-16.5,-3.2) 355(-14.6,-4) 356(-22.2,-2.4) 357(-20.3,-3.2) 358(-18.4,-4) 359(-16.5,-4.8) 360(-14.6,-5.6) 361(-22.2,-4) 362(-20.3,-4.8) 363(-18.4,-5.6) 364(-16.5,-6.4) 365(-14.6,-7.2) 366(-22.2,-5.6) 367(-20.3,-6.4) 368(-18.4,-7.2) 369(-16.5,-8) 370(-14.6,-8.8) 371(-22.2,-7.2) 372(-20.3,-8) 373(-18.4,-8.8) 374(-16.5,-9.6) 375(-22.2,-8.8) 376(-20.3,-9.6) 377(-18.4,-10.4) 378(-16.5,-11.2) 379(-22.2,-10.4) 380(-20.3,-11.2) 381(-18.4,-12) 382(-22.2,-12) 383(-20.3,-12.8) 384(-18.4,-13.6) 385(-22.2,-13.6) 386(-20.3,-14.4) 387(-22.2,-15.2) 388(-20.3,-16) 389(-22.2,-16.8) 390(-22.2,-18.4)
  round 1.2 smd: 391(-10,-7.5) 392(-7.5,-7.5) 393(-5,-7.5) 394(-2.5,-7.5) 395(0,-7.5) 396(2.5,-7.5) 397(5,-7.5) 398(7.5,-7.5) 399(10,-7.5) 400(-10,-5) 401(-7.5,-5) 402(-5,-5) 403(-2.5,-5) 404(0,-5) 405(2.5,-5) 406(5,-5) 407(7.5,-5) 408(10,-5) 409(-10,-2.5) 410(-7.5,-2.5) 411(-5,-2.5) 412(-2.5,-2.5) 413(0,-2.5) 414(2.5,-2.5) 415(5,-2.5) 416(7.5,-2.5) 417(10,-2.5) 418(-10,0) 419(-7.5,0) 420(-5,0) 421(-2.5,0) 422(0,0) 423(2.5,0) 424(5,0) 425(7.5,0) 426(10,0) 427(-10,2.5) 428(-7.5,2.5) 429(-5,2.5) 430(-2.5,2.5) 431(0,2.5) 432(2.5,2.5) 433(5,2.5) 434(7.5,2.5) 435(10,2.5) 436(-10,5) 437(-7.5,5) 438(-5,5) 439(-2.5,5) 440(0,5) 441(2.5,5) 442(5,5) 443(7.5,5) 444(10,5) 445(-10,7.5) 446(-7.5,7.5) 447(-5,7.5) 448(-2.5,7.5) 449(0,7.5) 450(2.5,7.5) 451(5,7.5) 452(7.5,7.5) 453(10,7.5)
SGM2036S-2_8XN5G_TR_PINS5_2D92X1D6
  rect 0.69x0.99 smd: 1(-0.95,-1.295) 2(0,-1.295) 3(0.95,-1.295) 4(0.95,1.295) 5(-0.95,1.295)
SGM2036S-ADJXN5G_TR_PINS5_2D92X1D6
  rect 0.69x0.99 smd: 1(-0.95,-1.295) 2(0,-1.295) 3(0.95,-1.295) 4(0.95,1.295) 5(-0.95,1.295)
SGM3756YTDI6G_TR_PINS7_2X2
  rect 0.24x0.65 smd: 1(-0.65,-0.975) 2(0,-0.975) 3(0.65,-0.975) 4(0.65,0.975) 5(0,0.975) 6(-0.65,0.975)
  rect 1.4x0.8 smd: 7(0,0)
SILKLABEL_25_00X10_00
  round 0 smd: 1(0,0)
SIT3088EESA
  rect 0.4x1.16 smd: 1(-1.905,-2.52) 2(-0.635,-2.52) 3(0.635,-2.52) 4(1.905,-2.52) 5(1.905,2.52) 6(0.635,2.52) 7(-0.635,2.52) 8(-1.905,2.52)
SMAJ18CA
  rect 1.52x1.63 smd: 1(-2.035,0) 2(2.035,0)
SOD-323
  rect 0.9x0.9 smd: 1(-1.05,0) 2(1.05,0)
SSAJ120100
  rect 0.6x0.51 smd: 1(-1,1.355) 2(0,1.355) 3(1,1.355)
  rect 0.9x0.7 smd: 4(-3,0) 5(3,0)
THDP08-060AB1_PINS4_7D5X8D7
  round 1.6 hole 1: 1(-2.25,0.5) 2(2.25,0.5)
  round 2.4 hole 1.4: 3(-3.5,3) 4(3.5,3)
TP-NUU-M3_15X6_00X4_35MM
  round 6 hole 3.15: 1(0,0)
TP_1_00
  round 1 smd: 1(0,0)
TP_2_20
  round 2.2 smd: 1(0,0)
TXB0104PWR
  rect 0.35x1.6 smd: 1(-1.95,-2.8) 2(-1.3,-2.8) 3(-0.65,-2.8) 4(0,-2.8) 5(0.65,-2.8) 6(1.3,-2.8) 7(1.95,-2.8) 8(1.95,2.8) 9(1.3,2.8) 10(0.65,2.8) 11(0,2.8) 12(-0.65,2.8) 13(-1.3,2.8) 14(-1.95,2.8)
UM3232EEUE
  rect 0.35x1.35 smd: 1(-2.275,-2.9) 2(-1.625,-2.9) 3(-0.975,-2.9) 4(-0.325,-2.9) 5(0.325,-2.9) 6(0.975,-2.9) 7(1.625,-2.9) 8(2.275,-2.9) 9(2.275,2.9) 10(1.625,2.9) 11(0.975,2.9) 12(0.325,2.9) 13(-0.325,2.9) 14(-0.975,2.9) 15(-1.625,2.9) 16(-2.275,2.9)
W-N3-SC90-012
  round 1.3 hole 0.7: 1(-3.5,2.89) 2(-1,2.89) 3(1,2.89) 4(3.5,2.89) 5(4,4.39) 6(2,4.39) 7(0,4.39) 8(-2,4.39) 9(-4,4.39) 10(-3.5,6.09) 11(-1,6.09) 12(1,6.09) 13(3.5,6.09) 14(4,7.59) 15(2,7.59) 16(0,7.59) 17(-2,7.59) 18(-4,7.59)
  round 3.5 hole 2.3: 19(-6.57,6.57) 20(-6.57,0.89) 21(6.57,0.89) 22(6.57,6.57)
W-USB2-SZ90-A10_PINS12_17D85X14D3
  oval 1.4x3.7 hole 0.8x3.1: 1(-6.4,7.375) 2(-6.4,1.695) 3(6.4,1.695) 4(6.4,7.375)
  round 1.52 hole 0.92: A1(-3.5,7.025) A2(-1,7.025) A3(1,7.025) A4(3.5,7.025) B1(-3.5,4.405) B2(-1,4.405) B3(1,4.405) B4(3.5,4.405)
WMM7037ATSN0
  round 0.8 smd: 1(0.85,1.23) 2(0.85,-1.23) 3(-0.85,-1.23) 4(-0.85,1.23)
WPM3027
  rect 0.45x0.25 smd: 1(0.375,-0.225) 2(0.375,0.225)
  rect 0.45x0.7 smd: 3(-0.325,0)
WS4612EDA-5_TR
  rect 0.8x0.55 smd: 1(-1.15,0.95) 2(-1.15,0) 3(-1.15,-0.95) 4(1.15,-0.95) 5(1.15,0.95)
WX4558105890
  rect 0.4x1.35 smd: 1(-1.3,2.675) 2(-0.65,2.675) 3(0,2.675) 4(0.65,2.675) 5(1.3,2.675)
  rect 2.1x1.6 smd: 6(3.1,2.55) 7(-3.1,2.55)
  rect 1.9x1.9 smd: 8(-1.2,0) 9(1.2,0)
  oval 1.1x1.8 hole 0.5x1.2: 10(3.2,0) 11(-3.2,0)
WXHDMI2034A36
  rect 0.34x2.2 smd: 1(4.5,5.55) 2(4,5.55) 3(3.5,5.55) 4(3,5.55) 5(2.5,5.55) 6(2,5.55) 7(1.5,5.55) 8(1,5.55) 9(0.5,5.55) 10(0,5.55) 11(-0.5,5.55) 12(-1,5.55) 13(-1.5,5.55) 14(-2,5.55) 15(-2.5,5.55) 16(-3,5.55) 17(-3.5,5.55) 18(-4,5.55) 19(-4.5,5.55)
  oval 2x3.8 hole 0.8x2.6: 20(-7.25,4.55) 23(7.25,4.55)
  oval 2x3 hole 0.8x1.4: 21(-7.25,-1.45) 22(7.25,-1.45)
X1B000311000100_PINS10_3D2X2D5
  rect 0.7x0.9 smd: 1(-1.55,-1) 5(1.55,-1) 6(1.55,1) 10(-1.55,1)
  rect 0.4x0.9 smd: 2(-0.7,-1) 3(0,-1) 4(0.7,-1) 7(0.7,1) 8(0,1) 9(-0.7,1)
YT8531C
  custom 0.05x0.05 smd: 1(-2.35,1.8) 10(-2.35,-1.8) 11(-1.8,-2.35) 20(1.8,-2.35) 21(2.35,-1.8) 30(2.35,1.8) 31(1.8,2.35) 40(-1.8,2.35)
  rect 0.5x0.2 smd: 2(-2.35,1.4) 3(-2.35,1) 4(-2.35,0.6) 5(-2.35,0.2) 6(-2.35,-0.2) 7(-2.35,-0.6) 8(-2.35,-1) 9(-2.35,-1.4) 22(2.35,-1.4) 23(2.35,-1) 24(2.35,-0.6) 25(2.35,-0.2) 26(2.35,0.2) 27(2.35,0.6) 28(2.35,1) 29(2.35,1.4)
  rect 0.2x0.5 smd: 12(-1.4,-2.35) 13(-1,-2.35) 14(-0.6,-2.35) 15(-0.2,-2.35) 16(0.2,-2.35) 17(0.6,-2.35) 18(1,-2.35) 19(1.4,-2.35) 32(1.4,2.35) 33(1,2.35) 34(0.6,2.35) 35(0.2,2.35) 36(-0.2,2.35) 37(-0.6,2.35) 38(-1,2.35) 39(-1.4,2.35)
  custom 0.925x0.925 smd: 41(0,0)

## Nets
AVDD10_A: C0910.1 C0913.1 C0915.1 R0923.1 U0902.3(AVDDL1) U0902.8(AVDDL2) U0902.38(AVDDL3)
AVDD33_A: C0904.1 C0908.1 R0915.1 U0902.11(AVDD33_1) U0902.40(AVDD33_2)
DVDD0_1V1: B0202.2 C0201.1 C0210.1 J0201.1
DVDD1_1V1: B0203.2 C0202.1 C0214.1 J0202.1
DVDD3V3_A: C0906.1 C0911.2 C0922.1 R0904.1 R0907.1 R0908.2 R0938.1 R0942.1 R0950.2 R0953.1 R0954.1 R0956.1 U0902.29(DVDD33)
DVDD10_A: C0905.1 R0910.1 U0902.21(DVDDL)
DVDDRG_A: C0914.1 C0918.2 R0905.1 R0909.1 R0912.1 R0919.1 R0921.1 R0928.1 R0947.1 R0950.1 U0902.28(DVDD_RGMII)
GND: BAT1201.2 C0102.1 C0103.1 C0104.1 C0105.1 C0106.1 C0107.1 C0108.1 C0109.1 C0110.1 C0112.1 C0115.1 C0116.1 C0118.1 C0119.1 C0121.1 C0122.1 C0123.1 C0124.1 C0126.1 C0127.1 C0128.1 C0201.2 C0202.2 C0203.2 C0204.1 C0205.1 C0206.2 C0207.1 C0208.1 C0209.1 C0210.2 C0212.1 C0213.1 C0214.2 C0215.1 C0216.1 C0217.1 C0301.1 C0303.1 C0319.1 C0352.2 C0353.2 C0354.2 C0355.2 C0362.1 C0363.1 C0401.1 C0402.1 C0403.2 C0404.2 C0406.2 C0407.2 C0408.2 C0409.2 C0410.1 C0412.2 C0413.1 C0501.1 C0502.1 C0504.2 C0506.1 C0507.2 C0508.2 C0511.2 C0512.1 C0514.2 C0518.2 C0519.1 C0520.1 C0521.2 C0522.1 C0523.2 C0524.1 C0525.1 C0526.1 C0527.2 C0528.2 C0530.2 C0533.2 C0535.1 C0601.1 C0602.1 C0603.1 C0604.1 C0605.2 C0606.1 C0607.1 C0609.1 C0611.1 C0613.1 C0614.1 C0615.1 C0617.1 C0619.1 C0620.2 C0621.2 C0622.1 C0623.2 C0624.1 C0701.1 C0702.2 C0703.2 C0704.1 C0705.2 C0706.1 C0707.1 C0708.1 C0709.1 C0710.2 C0711.1 C0712.1 C0713.1 C0715.1 C0716.2 C0717.1 C0801.1 C0802.1 C0803.1 C0804.1 C0805.1 C0806.1 C0901.2 C0902.1 C0903.2 C0904.2 C0905.2 C0906.2 C0907.2 C0908.2 C0910.2 C0911.1 C0912.1 C0913.2 C0914.2 C0915.2 C0916.1 C0917.1 C0918.1 C0919.2 C0920.2 C0921.1 C0922.2 C0986.2 C0987.2 C0988.2 C1001.1 C1003.1 C1004.2 C1005.1 C1006.1 C1007.2 C1008.2 C1009.2 C1010.1 C1011.2 C1012.2 C1013.1 C1014.2 C1015.1 C1018.1 C1021.1 C1023.1 C1024.1 C1025.2 C1055.1 C1056.1 C1099.1 C1101.1 C1102.2 C1103.1 C1104.1 C1106.1 C1108.2 C1110.1 C1111.2 C1201.1 C1202.1 C1203.1 C1204.1 C1302.1 C1303.2 C1304.1 C1306.1 C1333.2 C1401.1 C1402.1 D0101.2 D0102.1 D0301.3(GND1) D0301.8(GND2) D0302.2 D0303.2 D0353.2 D0354.2 D0355.2 D0356.2 D0357.2 D0358.2 D0359.3(GND1) D0359.8(GND2) D0406.2 D0407.2 D0408.2 D0410.2 D0501.2(E) D0502.5(GND1) D0502.6(GND2) D0503.2(E) D0504.1 D0505.2(E) D0506.5(GND1) D0506.6(GND2) D0507.2(E) D0509.1 D0510.1 D0511.5(GND1) D0511.6(GND2) D0512.5(GND1) D0512.6(GND2) D0513.1 D0514.5(GND1) D0514.6(GND2) D0601.2 D0602.2 D0603.2 D0605.2 D0606.2 D0608.2 D0701.2(E) D0702.2 D0703.2(E) D0704.2 D0705.1 D0801.2 D0802.2 D0803.2 D0804.2 D0806.2 D0807.2 D0808.2 D0809.2 D0810.2 D0902.2(E) D0904.3(GND1) D0904.8(GND2) D0905.2(E) D0906.3(GND1) D0906.8(GND2) D1001.2 D1002.2 D1003.2 D1004.2 D1050.2 D1051.2 D1104.2 D1106.2 D1201.1 D1202.2 D1255.1 D1256.1 D1301.1 D1301.2 J0101.2 J0101.3 J0101.4 J0101.5 J0201.4 J0201.8 J0201.11 J0201.15 J0201.18 J0201.23 J0201.26 J0201.27 J0202.4 J0202.8 J0202.11 J0202.15 J0202.18 J0202.23 J0202.26 J0202.27 J0301.4(GND1) J0301.7(GND-DRAIN1) J0301.13(GND2) J0301.16(GND-DRAIN2) J0301.19 J0301.20 J0301.21 J0301.22 J0302.5(GND1) J0302.6(GND2) J0302.7(GND3) J0302.8(GND4) J0302.9(GND5) J0302.10(GND6) J0302.11(GND7) J0401.2(D2_SHIELD) J0401.5(D1_SHIELD) J0401.8(D0_SHIELD) J0401.11(CLK_SHIELD) J0401.17(CEC_GND) J0401.20(GND1) J0401.21(GND2) J0401.22(GND3) J0401.23(GND4) J0402.4 J0402.7 J0402.8 J0403.7 J0403.10 J0403.13 J0403.16 J0403.19 J0403.22 J0403.25 J0403.30 J0403.41 J0403.42 J0501.12(GND1) J0501.16(GND2) J0501.19(GND3) J0501.22(GND4) J0501.25(GND5) J0501.28(GND6) J0501.31 J0501.32 J0501.33 J0501.34 J0502.5 J0502.12 J0502.15 J0502.18 J0502.21 J0502.24 J0502.27 J0502.31 J0502.32 J0503.5(GND) J0503.7 J0503.8 J0601.1 J0601.2 J0601.3 J0601.4 J0601.A4(GND1) J0601.B4(GND2) J0701.4 J0701.9 J0701.15 J0701.18 J0701.21 J0701.26 J0701.27 J0701.29 J0701.34 J0701.35 J0701.37 J0701.40 J0701.43 J0701.50 J0701.53 J0701.54 J0702.1(GND1) J0702.2(GND2) J0702.3(GND3) J0702.4(GND4) J0801.1(GND1) J0801.2(GND2) J0801.3(GND3) J0801.4(GND4) J0801.P6(VSS) J0802.1(GND1) J0802.2(GND2) J0802.3(GND3) J0802.4(GND4) J0802.C5(GND5) J1002.1(GND) J1002.5(DETECT2) J1101.5 J1101.6 J1201.1 J1201.15 PCB1201.1(GND) Q0402.2(E) Q0403.2(E) Q0404.2(E) Q1101.2(E) Q1102.2(E) R0101.2 R0103.1 R0108.1 R0110.1 R0112.2 R0114.2 R0203.1 R0204.1 R0219.1 R0223.1 R0224.1 R0227.2 R0228.2 R0309.1 R0312.1 R0313.1 R0413.1 R0422.1 R0425.2 R0507.1 R0512.1 R0516.1 R0518.1 R0519.1 R0530.1 R0603.1 R0607.1 R0610.1 R0613.2 R0615.1 R0617.1 R0618.1 R0624.1 R0712.1 R0718.1 R0722.2 R0725.1 R0727.1 R0901.2 R0902.2 R0913.2 R0914.2 R0916.2 R0917.2 R0922.2 R0926.2 R0927.1 R0929.2 R0940.2 R0944.2 R0946.2 R0952.2 R1004.1 R1005.2 R1007.1 R1012.1 R1015.1 R1018.2 R1024.1 R1099.1 R1121.1 R1129.1 R1132.2 R1134.1 R1456.1 R1467.2 R1469.1 S0301.3(2) S0301.4 S0301.5 S1201.3(2) S1201.4 S1201.5 S1202.1 S1202.3 S1202.4 TP0104.1 TP1202.1 TP1303.1 TP1304.1 U0101.3(GND) U0103.3(GND) U0104.3(GND) U0201.5(GND1) U0201.6(GND2) U0202.2(GND) U0203.2(GND) U0204.2(GND) U0205.2(GND) U0206.5(GND1) U0206.6(GND2) U0207.5(GND1) U0207.6(GND2) U0208.5(GND1) U0208.6(GND2) U0209.5(GND1) U0209.6(GND2) U0210.5(GND1) U0210.6(GND2) U0304.2(GND) U0403.5(GND1) U0403.6(GND2) U0404.5(GND1) U0404.6(GND2) U0408.5(GND1) U0408.6(GND2) U0409.3(GND1) U0409.7(GND2) U0411.5(GND1) U0411.6(GND2) U0501.2(GND) U0502.2(GND) U0503.2(GND2) U0503.5(GND1) U0504.3(GND1) U0504.7(GND2) U0601.2(GND) U0602.2(GND) U0603.2(GND) U0604.3(GND) U0701.3(GND) U0702.7(GND) U0902.41(GND) U1001.17(PGND) U1002.2(GND1) U1002.3(GND2) U1101.5(GND) U1102.D2(GND) U1103.15(GND) U1201.1 U1202.1 U1203.1 U1204.7(GND) U1205.1 U1301.1(GND1) U1301.13(GND2) U1301.14(GND3) U1301.18(GND4) U1301.21(GND5) U1301.22(GND6) U1301.44(GND7) U1301.48(GND8) U1301.51(GND9) U1301.52(GND10) U1301.65(GND11) U1301.74(GND12) U1301.76(GND13) U1301.77(GND14) U1301.78(GND15) U1301.93(GND16) U1301.94(GND17) U1301.95(GND18) U1301.96(GND19) U1301.99(GND20) U1301.105(GND21) U1301.106(GND22) U1301.114(GND23) U1301.115(GND24) U1301.116(GND25) U1301.119(GND26) U1301.120(GND27) U1301.128(GND28) U1301.133(GND29) U1301.138(GND30) U1301.142(GND31) U1301.143(GND32) U1301.144(GND33) U1301.145(GND34) U1301.146(GND35) U1301.149(GND36) U1301.154(GND37) U1301.158(GND38) U1301.162(GND39) U1301.166(GND40) U1301.167(GND41) U1301.184(GND42) U1301.186(GND43) U1301.187(GND44) U1301.188(GND45) U1301.189(GND46) U1301.190(GND47) U1301.191(GND48) U1301.193(GND49) U1301.194(GND50) U1301.195(GND51) U1301.196(GND52) U1301.199(GND53) U1301.200(GND54) U1301.202(GND55) U1301.203(GND56) U1301.207(GND57) U1301.211(GND58) U1301.212(GND59) U1301.216(GND60) U1301.224(GND61) U1301.235(GND62) U1301.237(GND63) U1301.238(GND64) U1301.241(GND65) U1301.259(GND66) U1301.263(GND67) U1301.266(GND68) U1301.274(GND69) U1301.280(GND70) U1301.283(GND71) U1301.285(GND72) U1301.300(GND73) U1301.301(GND74) U1301.309(GND75) U1301.311(GND76) U1301.323(GND77) U1301.324(GND78) U1301.325(GND79) U1301.326(GND80) U1301.338(GND81) U1301.341(GND82) U1301.350(GND83) U1301.353(GND84) U1301.356(GND85) U1301.372(GND86) U1301.373(GND87) U1301.375(GND88) U1301.390(GND89) U1301.391(GND90) U1301.392(GND91) U1301.393(GND92) U1301.394(GND93) U1301.395(GND94) U1301.396(GND95) U1301.397(GND96) U1301.398(GND97) U1301.399(GND98) U1301.400(GND99) U1301.401(GND100) U1301.402(GND101) U1301.403(GND102) U1301.404(GND103) U1301.405(GND104) U1301.406(GND105) U1301.407(GND106) U1301.408(GND107) U1301.409(GND108) U1301.410(GND109) U1301.411(GND110) U1301.412(GND111) U1301.413(GND112) U1301.414(GND113) U1301.415(GND114) U1301.416(GND115) U1301.417(GND116) U1301.418(GND117) U1301.419(GND118) U1301.420(GND119) U1301.421(GND120) U1301.422(GND121) U1301.423(GND122) U1301.424(GND123) U1301.425(GND124) U1301.426(GND125) U1301.427(GND126) U1301.428(GND127) U1301.429(GND128) U1301.430(GND129) U1301.431(GND130) U1301.432(GND131) U1301.433(GND132) U1301.434(GND133) U1301.435(GND134) U1301.436(GND135) U1301.437(GND136) U1301.438(GND137) U1301.439(GND138) U1301.440(GND139) U1301.441(GND140) U1301.442(GND141) U1301.443(GND142) U1301.444(GND143) U1301.445(GND144) U1301.446(GND145) U1301.447(GND146) U1301.448(GND147) U1301.449(GND148) U1301.450(GND149) U1301.451(GND150) U1301.452(GND151) U1301.453(GND152) U1401.1(NC) U1401.2(GND1) U1401.4(GND2) X0901.2(GND1) X0901.4(GND2)
GND_FIELD SIGNAL: C0901.1 C0909.1 C0920.1 D0901.2 D0903.2 J0901.15(S1) J0901.16(S2) R0946.1
VBATT: C0107.2 C0119.2 C0123.2 C0204.2 C0205.2 C0213.2 C0215.2 C0501.2 C0502.2 C0512.2 C0530.1 J0102.1 L0103.2 L0501.1 R0115.1 R0120.2 R0504.2 R0510.2 R0515.2 R1211.1 U0202.1(IN) U0203.1(IN) U0204.3(IN) U0205.1(IN) U0501.1(IN) U0502.1(IN) U0503.4(VIN) U0504.6(VIN)
VBATT_M: C1302.2 C1303.1 C1304.2 C1306.2 C1333.1 D1301.3 J0102.2 R0120.1 R1455.2 TP1301.1 TP1302.1 U1301.147(VBAT5) U1301.148(VBAT6) U1301.151(VBAT7) U1301.152(VBAT8) U1301.153(VBAT1) U1301.156(VBAT2) U1301.157(VBAT3) U1301.161(VBAT4)
VBUS_USB_HOST1: C0362.2 C0363.2 C0604.2 C0609.2 D0358.1 J0301.10(VBUS2) R0678.2 U0602.1(OUT)
VBUS_USB_HOST2: C0603.2 C0605.1 C0606.2 C0620.1 D0602.1 J0601.A1(VBUS1) R0677.2 U0601.1(OUT)
VBUS_USB_HOST3: C0617.2 C0619.2 C0621.1 C0623.1 D0605.1 J0601.B1(VBUS2) R0666.2 U0603.1(OUT)
VCC3V3_PMU: R0809.1 U1301.129(VCC_PMUIO1)
VCC3V3_SD: R0813.1 U1301.262(SD_VDD)
VCC5V0_SYS: B0101.2 U1301.176(VCC_SPK_HP)
VCC5V0_USB: C0319.2 C0601.2 C0602.2 C0607.2 C0611.2 C0613.2 C0615.2 L0601.2 R0305.1 R0308.1 R0366.1 R0602.1 R0604.1 R0606.1 R0612.1 R0614.1 R0622.1 R0623.1 R0666.1 R0677.1 R0678.1 U0304.5(IN) U0601.5(IN) U0602.5(IN) U0603.5(IN)
VCC_1V8: R1022.2 U1301.139(BUCK5_1V8)
VCC_PMUIO2: R0508.2 R0517.2 R1204.2 R1205.1 U1301.355(VCC_PMUIO2)
VCCA1V8_IMAGE: R0511.1 R1466.2 R1468.2 U1301.124(LDO9_1V8)
VCCIO4: R1202.1 R1203.2 R1206.2 U0407.1(G) U0410.1(G) U1301.180(VCCIO4)
VCCIO5: C0702.1 C0716.1 C1103.2 C1108.1 R0705.2 R1017.2 R1107.2 U0702.1(VCCA) U1102.B2(VREF_A) U1301.371(VCCIO5)
VCCIO6: R0941.1 U1301.302(VCCIO6)
VCCIO7: D0404.1(G) R0405.2 R0417.2 R0428.2 U0405.1(G) U0413.1(G) U1301.389(VCCIO7)
VCCIO_ACODEC: B1002.1 Q0405.1(G) R0403.2 U1301.282(VCCIO1)
VDD_2V8: B0503.2 C0507.1 C0508.1 J0501.14(VIO28) TP0504.1
VDD_AF0_2V8: C0203.1 J0201.3 R0229.2
VDD_AF1_2V8: C0206.1 J0202.3 R0209.2
4G_PWREN_H_GPIO0_C6: D0501.1(B) U1301.370(GPIO0_C6)
4G_USIM_CLK: J0701.12 R0810.1
4G_USIM_DATA: J0701.10 R0808.1
4G_USIM_DET: D0803.6 J0701.44 J0802.CD R0866.2
4G_USIM_RTS: J0701.14 R0803.1
4G_USIM_VDD: C0801.2 D0803.1 J0701.8 J0802.C1(VCC) R0804.2
50OHM_ANTWIFI0: C1402.2 R1407.2 U1401.3(SIG)
50OHM_GMAC1_MCLKINOUT_M1: R0926.1 R0934.2 U1301.278(RGMII1_MCLK)
50OHM_GMAC1_RXCLK_M1: R0920.2 U1301.304(RGMII1_RX_CLK)
50OHM_GMAC1_RXD0_M1: R0906.2 U1301.296(RGMII1_RX0)
50OHM_GMAC1_RXD1_M1: R0955.2 U1301.294(RGMII1_RX1)
50OHM_GMAC1_RXD2_M1: R0903.2 U1301.308(RGMII1_RX2)
50OHM_GMAC1_RXD3_M1: R0932.2 U1301.307(RGMII1_RX3)
50OHM_GMAC1_RXDV_CRS_M1: R0945.2 U1301.293(RGMII1_RX_CTL)
50OHM_GMAC1_TXCLK: R1307.2 U1301.306(RGMII1_TX_CLK)
50OHM_GMAC1_TXCLK_M1: R1307.1 U0902.20(TX_CLK)
50OHM_GMAC1_TXD0: R1302.2 U1301.305(RGMII1_TX0)
50OHM_GMAC1_TXD0_M1: R1302.1 U0902.18(TXD0)
50OHM_GMAC1_TXD1: R1303.2 U1301.303(RGMII1_TX1)
50OHM_GMAC1_TXD1_M1: R1303.1 U0902.17(TXD1)
50OHM_GMAC1_TXD2: R1304.2 U1301.312(RGMII1_TX2)
50OHM_GMAC1_TXD2_M1: R1304.1 U0902.16(TXD2)
50OHM_GMAC1_TXD3: R1305.2 U1301.310(RGMII1_TX3)
50OHM_GMAC1_TXD3_M1: R1305.1 U0902.15(TXD3)
50OHM_GMAC1_TXEN: R1306.2 U1301.298(RGMII1_TX_CTL)
50OHM_GMAC1_TXEN_M1: R1306.1 U0902.19(TX_CTL)
50OHM_RXC/PHYAD1_A: R0917.1 R0919.2 R0920.1 U0902.27(RX_CLK/PHYAD1)
50OHM_RXCTL/PHYAD2_A: R0905.2 R0940.1 R0945.1 U0902.26(RX_CTL/PHYAD2)
50OHM_RXD0/RXDLY_A: R0906.1 R0928.2 R0952.1 U0902.25(RXD0/RXDLY)
50OHM_RXD1/CFG_MODEO_A: R0921.2 R0944.1 R0955.1 U0902.24(RXD1/TXDLY)
50OHM_RXD2/CFG_MODE1_A: R0903.1 R0909.2 R0916.1 U0902.23(RXD2/PLLOFF)
50OHM_RXD3/CFG_MODE2_A: R0902.1 R0912.2 R0932.1 U0902.22(RXD3/PHYAD0)
50OHM_SDMMC0_CLK: R0811.1 U1301.252(SD_CLK)
50OHM_SDMMC0_CLK1: D0801.1 J0801.P5(CLK) R0811.2
50OHM_SDMMC0_CMD: R0805.1 U1301.247(SD_CMD)
50OHM_SDMMC0_CMD1: D0809.1 J0801.P3(CMD) R0805.2
50OHM_SDMMC0_D0: R0801.1 U1301.246(SD_DATA0)
50OHM_SDMMC0_D0_1: D0804.1 J0801.P7(DAT0) R0801.2
50OHM_SDMMC0_D1: R0814.1 U1301.251(SD_DATA1)
50OHM_SDMMC0_D1_1: D0810.1 J0801.P8(DAT1) R0814.2
50OHM_SDMMC0_D2/ARMJTAG_TCK: R0802.1 U1301.256(SD_DATA2)
50OHM_SDMMC0_D2/ARMJTAG_TCK1: D0802.1 J0801.P1(DAT2) R0802.2
50OHM_SDMMC0_D3/ARMJTAG_TMS: R0806.1 U1301.257(SD_DATA3)
50OHM_SDMMC0_D3/ARMJTAG_TMS1: D0807.1 J0801.P2(CD/DAT3) R0806.2
50OHM_WIFI_ANT0: C1401.2 R1407.1 U1301.206(ANT_WIFI/BT)
90OHM_DM: D0704.1 J0701.36 L0702.3
90OHM_DP: D0702.1 J0701.38 L0702.4
90OHM_USB2_HOST2_DM: R0601.1 R0698.1 U1301.292(USB2_DM)
90OHM_USB2_HOST2_DM_A: D0608.1 J0601.A2(D-1) R0601.2
90OHM_USB2_HOST2_DM_B: L0702.1 R0698.2
90OHM_USB2_HOST2_DP: R0608.1 R0699.1 U1301.289(USB2_DP)
90OHM_USB2_HOST2_DP_A: D0603.1 J0601.A3(D+1) R0608.2
90OHM_USB2_HOST2_DP_B: L0702.2 R0699.2
90OHM_USB2_HOST3_DM: R0611.1 U1301.297(USB3_DM)
90OHM_USB2_HOST3_DM_A: D0606.1 J0601.B2(D-2) R0611.2
90OHM_USB2_HOST3_DP: R0616.1 U1301.295(USB3_DP)
90OHM_USB2_HOST3_DP_A: D0601.1 J0601.B3(D+2) R0616.2
90OHM_USB3_HOST1_DM: R0621.1 U1301.83(USB1_DM)
90OHM_USB3_HOST1_DM_A: D0357.1 J0301.11(D2-) R0621.2
90OHM_USB3_HOST1_DP: R0619.1 U1301.79(USB1_DP)
90OHM_USB3_HOST1_DP_A: D0356.1 J0301.12(D2+) R0619.2
90OHM_USB3_HOST1_SSRXN: R0341.2 U1301.92(USB1_SS_RX_M)
90OHM_USB3_HOST1_SSRXN_A1: D0359.1(I/O1) D0359.10(NC4) J0301.14(STDA-SSR2-) R0341.1
90OHM_USB3_HOST1_SSRXP: R0340.2 U1301.89(USB1_SS_RX_P)
90OHM_USB3_HOST1_SSRXP_A1: D0359.2(I/O2) D0359.9(NC3) J0301.15(STDA-SSR2+) R0340.1
90OHM_USB3_HOST1_SSTXN: C0361.2 U1301.88(USB1_SS_TX_M)
90OHM_USB3_HOST1_SSTXN_A1: C0361.1 D0359.4(I/O3) D0359.7(NC2) J0301.17(STDA-SST2-)
90OHM_USB3_HOST1_SSTXP: C0360.2 U1301.84(USB1_SS_TX_P)
90OHM_USB3_HOST1_SSTXP_A1: C0360.1 D0359.5(I/O4) D0359.6(NC1) J0301.18(STDA-SST2+)
90OHM_USB3_OTG0_DM: D0302.1 J0302.2(USB_DM) TP0301.1 U1301.113(USB0_DM)
90OHM_USB3_OTG0_DP: D0303.1 J0302.3(USB_DP) TP0302.1 U1301.112(USB0_DP)
90OHM_USB3_OTG0_SSRX_N: D0301.5(I/O4) D0301.6(NC1) J0301.5(STDA-SSR1-) R0322.1
90OHM_USB3_OTG0_SSRX_P: D0301.4(I/O3) D0301.7(NC2) J0301.6(STDA-SSR1+) R0323.1
90OHM_USB3_OTG0_SSRXN: R0322.2 U1301.110(USB0_SS_RX_M)
90OHM_USB3_OTG0_SSRXP: R0323.2 U1301.109(USB0_SS_RX_P)
90OHM_USB3_OTG0_SSTX_N: C0307.1 D0301.2(I/O2) D0301.9(NC3) J0301.8(STDA-SST1-)
90OHM_USB3_OTG0_SSTX_P: C0309.1 D0301.1(I/O1) D0301.10(NC4) J0301.9(STDA-SST1+)
90OHM_USB3_OTG0_SSTXN: C0307.2 U1301.108(USB0_SS_TX_M)
90OHM_USB3_OTG0_SSTXP: C0309.2 U1301.107(USB0_SS_TX_P)
100OHM_EDP_TX_AUXN: C0515.2 U1301.137(EDP_AUX_N)
100OHM_EDP_TX_AUXN1: C0515.1 J0502.13 R0505.2
100OHM_EDP_TX_AUXP: C0536.1 U1301.141(EDP_AUX_P)
100OHM_EDP_TX_AUXP1: C0536.2 J0502.14 R0519.2
100OHM_EDP_TX_D0N: C0509.2 U1301.132(EDP_ML0_N)
100OHM_EDP_TX_D0N1: C0509.1 J0502.17
100OHM_EDP_TX_D0P: C0534.1 U1301.136(EDP_ML0_P)
100OHM_EDP_TX_D0P1: C0534.2 J0502.16
100OHM_EDP_TX_D1N: C0531.2 U1301.127(EDP_ML1_N)
100OHM_EDP_TX_D1N1: C0531.1 J0502.20
100OHM_EDP_TX_D1P: C0513.1 U1301.131(EDP_ML1_P)
100OHM_EDP_TX_D1P1: C0513.2 J0502.19
100OHM_EDP_TX_D2N: C0529.2 U1301.122(EDP_ML2_N)
100OHM_EDP_TX_D2N1: C0529.1 J0502.23
100OHM_EDP_TX_D2P: C0505.1 U1301.126(EDP_ML2_P)
100OHM_EDP_TX_D2P1: C0505.2 J0502.22
100OHM_EDP_TX_D3N: C0510.2 U1301.117(EDP_ML3_N)
100OHM_EDP_TX_D3N1: C0510.1 J0502.26
100OHM_EDP_TX_D3P: C0532.1 U1301.121(EDP_ML3_P)
100OHM_EDP_TX_D3P1: C0532.2 J0502.25
100OHM_HDMI_CLK_N_1: J0401.12(CLK-) R0462.2 U0408.4
100OHM_HDMI_CLK_P_1: J0401.10(CLK+) R0461.2 U0408.3
100OHM_HDMI_TX0_N_1: J0401.9(D0-) R0460.2 U0404.4
100OHM_HDMI_TX0_P_1: J0401.7(D0+) R0459.2 U0404.3
100OHM_HDMI_TX0N_PORT: R0460.1 R1402.2 U0404.2
100OHM_HDMI_TX0N_PORT1: R1402.1 U1301.61(HDMI_TX0_M)
100OHM_HDMI_TX0P_PORT: R0459.1 R1401.2 U0404.1
100OHM_HDMI_TX0P_PORT1: R1401.1 U1301.62(HDMI_TX0_P)
100OHM_HDMI_TX1_N_1: J0401.6(D1-) R0458.2 U0411.4
100OHM_HDMI_TX1_P_1: J0401.4(D1+) R0457.2 U0411.3
100OHM_HDMI_TX1N_PORT: R0458.1 R1408.2 U0411.2
100OHM_HDMI_TX1N_PORT1: R1408.1 U1301.66(HDMI_TX1_M)
100OHM_HDMI_TX1P_PORT: R0457.1 R1403.2 U0411.1
100OHM_HDMI_TX1P_PORT1: R1403.1 U1301.67(HDMI_TX1_P)
100OHM_HDMI_TX2_N_1: J0401.3(D2-) R0466.2 U0403.4
100OHM_HDMI_TX2_P_1: J0401.1(D2+) R0455.2 U0403.3
100OHM_HDMI_TX2N_PORT: R0466.1 R1406.2 U0403.2
100OHM_HDMI_TX2N_PORT1: R1406.1 U1301.71(HDMI_TX2_M)
100OHM_HDMI_TX2P_PORT: R0455.1 R1405.2 U0403.1
100OHM_HDMI_TX2P_PORT1: R1405.1 U1301.72(HDMI_TX2_P)
100OHM_HDMI_TXCLKN_PORT: R0462.1 R1404.2 U0408.2
100OHM_HDMI_TXCLKN_PORT1: R1404.1 U1301.56(HDMI_CLK_M)
100OHM_HDMI_TXCLKP_PORT: R0461.1 R1409.2 U0408.1
100OHM_HDMI_TXCLKP_PORT1: R1409.1 U1301.57(HDMI_CLK_P)
100OHM_LAN0_MDI0N_A: D0906.2(I/O2) D0906.9(NC3) U0901.11 U0902.2(TRXN0)
100OHM_LAN0_MDI0P_A: D0906.1(I/O1) D0906.10(NC4) U0901.12 U0902.1(TRXP0)
100OHM_LAN0_MDI1N_A: D0906.5(I/O4) D0906.6(NC1) U0901.8 U0902.5(TRXN1)
100OHM_LAN0_MDI1P_A: D0906.4(I/O3) D0906.7(NC2) U0901.9 U0902.4(TRXP1)
100OHM_LAN0_MDI2N_A: D0904.2(I/O2) D0904.9(NC3) U0901.5 U0902.7(TRXN2)
100OHM_LAN0_MDI2P_A: D0904.1(I/O1) D0904.10(NC4) U0901.6 U0902.6(TRXP2)
100OHM_LAN0_MDI3N_A: D0904.5(I/O4) D0904.6(NC1) U0901.2 U0902.10(TRXN3)
100OHM_LAN0_MDI3P_A: D0904.4(I/O3) D0904.7(NC2) U0901.3 U0902.9(TRXP3)
100OHM_LAN0_RJ45_D0M_A: J0901.2(TA-) U0901.14
100OHM_LAN0_RJ45_D0P_A: J0901.1(TA+) U0901.13
100OHM_LAN0_RJ45_D1M_A: J0901.6(TB-) U0901.17
100OHM_LAN0_RJ45_D1P_A: J0901.3(TB+) U0901.16
100OHM_LAN0_RJ45_D2M_A: J0901.5(TC-) U0901.20
100OHM_LAN0_RJ45_D2P_A: J0901.4(TC+) U0901.19
100OHM_LAN0_RJ45_D3M_A: J0901.8(TD-) U0901.23
100OHM_LAN0_RJ45_D3P_A: J0901.7(TD+) U0901.22
100OHM_MIPI_CSI_RX_CLK0N: R0258.1 U0207.1 U1301.2(CSI_CLK0_N)
100OHM_MIPI_CSI_RX_CLK0N1: J0201.20 R0258.2 U0207.3
100OHM_MIPI_CSI_RX_CLK0P: R0257.1 U0207.2 U1301.3(CSI_CLK0_P)
100OHM_MIPI_CSI_RX_CLK0P1: J0201.19 R0257.2 U0207.4
100OHM_MIPI_CSI_RX_CLK1N: R0264.1 U0208.2 U1301.6(CSI_CLK1_N)
100OHM_MIPI_CSI_RX_CLK1N1: J0202.20 R0264.2 U0208.4
100OHM_MIPI_CSI_RX_CLK1P: R0263.1 U0208.1 U1301.9(CSI_CLK1_P)
100OHM_MIPI_CSI_RX_CLK1P1: J0202.19 R0263.2 U0208.3
100OHM_MIPI_CSI_RX_D0N: R0260.1 U0209.1 U1301.7(CSI_LN0_N)
100OHM_MIPI_CSI_RX_D0N1: J0201.22 R0260.2 U0209.3
100OHM_MIPI_CSI_RX_D0P: R0259.1 U0209.2 U1301.8(CSI_LN0_P)
100OHM_MIPI_CSI_RX_D0P1: J0201.21 R0259.2 U0209.4
100OHM_MIPI_CSI_RX_D1N: R0256.1 U0206.1 U1301.4(CSI_LN1_N)
100OHM_MIPI_CSI_RX_D1N1: J0201.10 R0256.2 U0206.3
100OHM_MIPI_CSI_RX_D1P: R0255.1 U0206.2 U1301.5(CSI_LN1_P)
100OHM_MIPI_CSI_RX_D1P1: J0201.9 R0255.2 U0206.4
100OHM_MIPI_CSI_RX_D2N: R0266.1 U0201.2 U1301.16(CSI_LN2_N)
100OHM_MIPI_CSI_RX_D2N1: J0202.22 R0266.2 U0201.4
100OHM_MIPI_CSI_RX_D2P: R0265.1 U0201.1 U1301.17(CSI_LN2_P)
100OHM_MIPI_CSI_RX_D2P1: J0202.21 R0265.2 U0201.3
100OHM_MIPI_CSI_RX_D3N: R0262.1 U0210.1 U1301.11(CSI_LN3_N)
100OHM_MIPI_CSI_RX_D3N1: J0202.10 R0262.2 U0210.3
100OHM_MIPI_CSI_RX_D3P: R0261.1 U0210.2 U1301.12(CSI_LN3_P)
100OHM_MIPI_CSI_RX_D3P1: J0202.9 R0261.2 U0210.4
100OHM_MIPI_DSI_TX0_CLKN: J0403.17 U1301.37(DSI0_CLK_N)
100OHM_MIPI_DSI_TX0_CLKP: J0403.18 U1301.36(DSI0_CLK_P)
100OHM_MIPI_DSI_TX0_D0N: J0403.8 U1301.47(DSI0_LN0_N)
100OHM_MIPI_DSI_TX0_D0P: J0403.9 U1301.46(DSI0_LN0_P)
100OHM_MIPI_DSI_TX0_D1N: J0403.11 U1301.42(DSI0_LN1_N)
100OHM_MIPI_DSI_TX0_D1P: J0403.12 U1301.41(DSI0_LN1_P)
100OHM_MIPI_DSI_TX0_D2N: J0403.14 U1301.32(DSI0_LN2_N)
100OHM_MIPI_DSI_TX0_D2P: J0403.15 U1301.31(DSI0_LN2_P)
100OHM_MIPI_DSI_TX0_D3N: J0403.20 U1301.27(DSI0_LN3_N)
100OHM_MIPI_DSI_TX0_D3P: J0403.21 U1301.26(DSI0_LN3_P)
100OHM_MIPI_DSI_TX1_CLKN: D0506.2 R0575.1 U1301.33(DSI1_CLK_N)
100OHM_MIPI_DSI_TX1_CLKN_1: D0506.4 J0501.30(MIPI_TCN) R0575.2
100OHM_MIPI_DSI_TX1_CLKP: D0506.1 R0574.1 U1301.29(DSI1_CLK_P)
100OHM_MIPI_DSI_TX1_CLKP_1: D0506.3 J0501.29(MIPI_TCP) R0574.2
100OHM_MIPI_DSI_TX1_D0N: D0502.2 R0573.1 U1301.43(DSI1_LN0_N)
100OHM_MIPI_DSI_TX1_D0N_1: D0502.4 J0501.27(MIPI_TDN0) R0573.2
100OHM_MIPI_DSI_TX1_D0P: D0502.1 R0572.1 U1301.39(DSI1_LN0_P)
100OHM_MIPI_DSI_TX1_D0P_1: D0502.3 J0501.26(MIPI_TDP0) R0572.2
100OHM_MIPI_DSI_TX1_D1N: D0512.2 R0571.1 U1301.38(DSI1_LN1_N)
